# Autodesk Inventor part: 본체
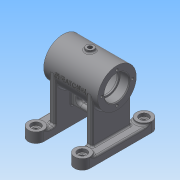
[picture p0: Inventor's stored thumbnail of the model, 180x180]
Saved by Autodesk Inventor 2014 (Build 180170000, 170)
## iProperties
Created: 2015-11
Part Number: 본체
Material: Generic
Document SubType Name: Modeling
Designer: 103-25
Density: 1 g/cm^3
Appearance: Default
Author: 103-25
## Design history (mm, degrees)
sketch "스케치1"
  geometry: L1 (-40, 40)-(-40, -40); L2 (-20, 40)-(-20, -40); A1 r 10 centre (-30, 40) between (-40, 40) and (-20, 40); A2 r 10 centre (-30, -40) between (-40, -40) and (-20, -40); 2 further points
  constraints: 4 end point, 4 point on circle, 4 tangent, 2 centre point, 1 equal radius, 1 horizontal alignment, 1 midpoint, 1 vertical alignment
  dimensions: "d3" = 20 diameter of A1; "d4" = 80 distance of A2.centre A1.centre; "d6" = 40 distance from line of point (0, 0) L1
extrude "돌출1" new body sketch "스케치1" distance "d7" = 10; taper "d8" = 0 deg
extrude "돌출2" join sketch "스케치1" distance "d9" = 13; taper "d10" = 0 deg
node "작업 평면2"
sketch "스케치2"
  geometry: L1 (40, 0)-(-40, 0) reference; C1 r 25 at (0, 68); 2 further points
  constraints: 1 centre point, 1 midpoint, 1 vertical alignment
  dimensions: "d12" = 50 diameter of C1; "d13" = 68 distance from line of L1 C1.centre
extrude "돌출3" join sketch "스케치2" stored distance "d14" = 70; taper "d15" = 0 deg
sketch "스케치3"
  geometry: L1 (-10, 0)-(-10, 80) reference; L2 (-68, 15)-(-10, 15); L3 (-68, 65)-(-10, 65); L4 (-10, 15)-(-10, 65); L5 (-68, 15)-(-68, 65); C1 r 25 at (-68, 40) reference; 1 further point
  constraints: 8 end point, 2 perpendicular, 2 point on line, 1 collinear, 1 midpoint, 1 parallel, 1 tangent
  dimensions: "d16" = 50 distance between parallel lines of L3 L2
extrude "돌출4" join sketch "스케치3" distance "d17" = 8; taper "d18" = 0 deg
node "작업 평면7"
sketch "스케치9"
  geometry: L1 (-35, 43)-(-35, 93) reference; L2 (-35, 93)-(35, 93) reference; L3 (35, 93)-(35, 43) reference; L4 (35, 43)-(28, 43) reference; L5 (28, 43)-(28, 10) reference; L6 (28, 10)-(40, 10) reference; L7 (40, 10)-(40, 0) reference; L8 (40, 0)-(20, 0) reference; L9 (20, 0)-(20, 43) reference; L10 (20, 43)-(-20, 43) reference; L11 (-20, 43)-(-20, 0) reference; L12 (-20, 0)-(-40, 0) reference; L13 (-40, 0)-(-40, 10) reference; L14 (-40, 10)-(-28, 10) reference; L15 (-28, 10)-(-28, 43) reference; L16 (-28, 43)-(-35, 43) reference; L17 (-20, 23)-(20, 23); L18 (-8, 36.5)-(8, 36.5); L19 (8, 29.5)-(-8, 29.5); L20 (-20, 23)-(-20, 53); L21 (-20, 53)-(20, 53); L22 (20, 53)-(20, 23); A1 r 3.5 centre (8, 33) between (8, 29.5) and (8, 36.5); A2 r 3.5 centre (-8, 33) between (-8, 36.5) and (-8, 29.5); 2 further points
  constraints: 12 end point, 4 point on circle, 4 tangent, 3 point on line, 2 centre point, 2 perpendicular, 1 collinear, 1 horizontal, 1 midpoint, 1 parallel, 1 vertical alignment
  dimensions: "d88" = 20 distance between parallel lines of L17 L10; "d89" = 23 dimension on A1 A2; "d90" = 33 distance from line of L8 A1.centre; "d91" = 3.5 radius of A1; "d123" = 30 distance between parallel lines of L17 L21
extrude "돌출7" join sketch "스케치9" stored distance "d92" = 8; taper "d93" = 0 deg
node "작업 평면3"
sketch "스케치4"
  geometry: C1 r 5 at (-30, 40); 1 further point
  constraints: 1 centre point, 1 coincident
  dimensions: "d20" = 10 diameter of C1
extrude "돌출5" join sketch "스케치4" stored distance "d21" = 10 (= d20); taper "d22" = 0 deg
node "작업 평면4"
sketch "스케치5"
  geometry: L1 (-68, 40)-(-43.751, 54); 3 further points
  constraints: 2 end point, 2 horizontal alignment, 1 coincident, 1 other
  dimensions: "d25" = 30 deg dimension on L1.start L1.end point (-43, 40); "d26" = 28 distance of L1.start L1.end
  node "투영된 루프1"
node "작업 평면6"
sketch "스케치7"
  geometry: C1 r 6 at (0, 0); 2 further points
  constraints: 1 centre point, 1 coincident
  dimensions: "d27" = 12 diameter of C1
extrude "돌출6" join sketch "스케치7" stored distance "d28" = 8; taper "d29" = 0 deg
hole "구멍1" diameter "d32" = 5.188; stored, may be unused: countersink angle "d36" = 90 deg, drill point angle "d38" = 118 deg; dims "d30" = 10, "d31" = 10, "d33" = 6, "d34" = 4, "d35" = 2, "d37" = 28
hole "구멍2" diameter "d41" = 5.188; stored, may be unused: countersink angle "d45" = 90 deg, drill point angle "d47" = 118 deg; dims "d39" = 10, "d40" = 10, "d42" = 6, "d43" = 4, "d44" = 2, "d46" = 28
hole "구멍3" diameter "d50" = 28; stored, may be unused: countersink angle "d54" = 90 deg, drill point angle "d56" = 0 deg; dims "d48" = 10, "d49" = 10, "d51" = 6, "d52" = 32, "d53" = 12, "d55" = 14
hole "구멍4" diameter "d59" = 28; stored, may be unused: countersink angle "d63" = 90 deg, drill point angle "d65" = 0 deg; dims "d57" = 10, "d58" = 10, "d60" = 6, "d61" = 32, "d62" = 12, "d64" = 14
hole "구멍5" diameter "d68" = 42; stored, may be unused: countersink angle "d72" = 90 deg, drill point angle "d74" = 0 deg; dims "d66" = 10, "d67" = 10, "d69" = 6, "d70" = 32, "d71" = 12, "d73" = 42
sketch "스케치8"
  geometry: C1 r 16 at (0, 0) reference; 2 further points
  constraints: 1 vertical alignment
  dimensions: "d75" = 20 distance of C1.centre point (0, 20)
hole "구멍6" sketch "스케치8" at (0, 20) diameter "d76" = 3.242; stored, may be unused: countersink angle "d80" = 90 deg, drill point angle "d82" = 118 deg; dims "d77" = 8, "d78" = 32, "d79" = 12, "d81" = 10
sketch "스케치10"
  geometry: C1 r 10 at (0, 0) reference; C2 r 10 at (0, 80) reference; C3 r 10 at (60, 80) reference; C4 r 10 at (60, 0) reference; 5 further points
  constraints: 4 coincident
hole "구멍7" sketch "스케치10" at (0, 80), (60, 80), (60, 0), (0, 0) diameter "d94" = 6; stored, may be unused: countersink angle "d98" = 90 deg, drill point angle "d100" = 118 deg; dims "d95" = 8, "d96" = 12, "d97" = 4, "d99" = 10
node "작업 평면8"
sketch "스케치11"
  geometry: L1 (-35, 25)-(35, 25) reference; L2 (-35, 25)-(-35, -25) reference; 2 further points
  constraints: 1 other
  dimensions: "d101" = 35 distance from line of L2 point (0, 0); "d102" = 25 distance from line of L1 point (0, 0)
feature "엠보싱1" sketch "스케치11" dims "d103" = 0.5, "d104" = 0
chamfer "모따기1" distance "d105" = 1; stored, may be unused: second distance "d106" = 2, angle "d107" = 45 deg
fillet "모깎기1" dims "d108" = 0.3, "d109" = 3.5
fillet "모깎기4" dims "d112" = 2
fillet "모깎기5" dims "d113" = 2
fillet "모깎기6" dims "d114" = 2
fillet "모깎기7" dims "d115" = 2
fillet "모깎기8" dims "d116" = 2
fillet "모깎기10" dims "d118" = 2
fillet "모깎기11" dims "d119" = 3
fillet "모깎기12" dims "d120" = 2
fillet "모깎기14" dims "d122" = 2
fillet "모깎기15" dims "d124" = 2
fillet "모깎기16" dims "d125" = 2
node "솔리드1"
mirror "대칭1"
mirror "대칭2"
pattern_circular "원형 패턴1" dims angle "d84" = 360 deg
mirror "대칭3"
node "작업 평면1"
node "절단 모서리 투영1"
other parameters: "d11" = 0, "d19" = -96, "d86" = 0
